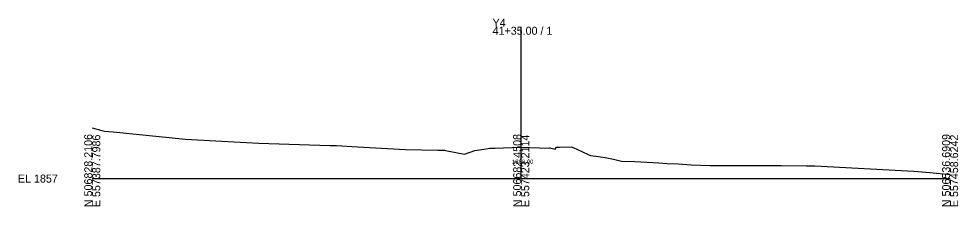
# Model space of a CAD drawing. Extents: x -26 to 1503, y -10 to 3040.
# Drawn here: x 1174.3 to 1502.8, y 490.3 to 556 of the extents above; entities that cross this region are included whole.
import ezdxf

# ---------------------------------------------------------------- set-up
doc = ezdxf.new("R2010")
doc.units = 0
for name, color, linetype in [('Exist Cross Section Cell', 7, 'Continuous'), ('Exist XS Ground Line', 7, 'Continuous'), ('Prop CMT Pvmt Course 1', 7, 'Continuous'), ('Prop CMT Shld Paved Course 1', 7, 'Continuous'), ('Prop XS Ditch Standard Text', 7, 'Continuous')]:
    doc.layers.add(name, color=color, linetype=linetype)

msp = doc.modelspace()

# ---------------------------------------------------------------- linework, layer by layer
at = {"layer": 'Exist Cross Section Cell'}
for p, q in [((1350, 500), (1350, 553.18)), ((1200, 500), (1350, 500)), ((1350, 500), (1500, 500))]:
    msp.add_line(p, q, dxfattribs=at)
at = {"layer": 'Exist XS Ground Line'}
msp.add_lwpolyline([(1200, 517.73), (1203.31, 516.86), (1204.3, 516.56), (1207.37, 516.33), (1232.64, 513.75), (1245.3, 513.12), (1258.23, 512.41), (1283.07, 511.61), (1285.43, 511.54), (1292.74, 511.12), (1309.49, 510.21), (1320.88, 509.96), (1322.85, 509.93), (1323.16, 509.92), (1323.51, 509.86), (1330.17, 508.53), (1333.84, 509.8), (1337.71, 510.46), (1339.04, 510.63), (1340.92, 510.7), (1349.8, 511.01), (1356.43, 510.8), (1359.87, 510.7), (1359.98, 510.71), (1361.86, 510.31), (1362.37, 510.97), (1363.38, 511.01), (1367.5, 511.15), (1368.43, 510.72), (1369.49, 510.29), (1373.45, 508.41), (1374.28, 508.12), (1377.1, 507.73), (1379.94, 507.29), (1382.28, 506.76), (1385.04, 506.07), (1389.78, 505.93), (1398.1, 505.55), (1401.08, 505.32), (1404.86, 505.2), (1409.44, 504.86), (1416.1, 504.6), (1435.15, 504.59), (1438.68, 504.56), (1440.95, 504.56), (1449.79, 504.46), (1451.75, 504.46), (1452.68, 504.46), (1487.35, 502.58), (1492.96, 502.14), (1500, 501.47)], dxfattribs=at)
at = {"layer": 'Prop CMT Pvmt Course 1'}
for points in [[(1350, 510.87), (1350, 511.12)], [(1350, 510.87), (1350, 511.12)], [(1360, 510.92), (1360, 510.67)]]:
    msp.add_lwpolyline(points, dxfattribs=at)
msp.add_lwpolyline([(1350, 510.87), (1350, 511), (1350, 511), (1350, 510.87)], close=True, dxfattribs=at)
msp.add_lwpolyline([(1350, 510.87), (1350, 511), (1350, 511), (1350, 510.87)], close=True, dxfattribs=at)
at = {"layer": 'Prop CMT Shld Paved Course 1'}
msp.add_lwpolyline([(1339.74, 510.66), (1340, 510.67)], dxfattribs=at)

# ---------------------------------------------------------------- texts
at = {"layer": 'Exist Cross Section Cell'}
for s, p in [('Y4', (1340, 553.18)), ('41+35.00 / 1', (1340, 550.38)), ('EL 1857', (1174, 498.6))]:
    msp.add_text(s, height=2.8, dxfattribs=at).set_placement(p)
for s, p in [('N 506828.2106', (1200, 490)), ('E 557387.7986', (1202.8, 490)), ('N 506682.4508', (1350, 490)), ('E 557423.2114', (1352.8, 490)), ('N 506536.6909', (1500, 490)), ('E 557458.6242', (1502.8, 490))]:
    msp.add_text(s, height=2.8, rotation=90, dxfattribs=at).set_placement(p)
at = {"layer": 'Prop XS Ditch Standard Text'}
msp.add_text('1868.00', height=1.5, dxfattribs=at).set_placement((1346.79, 505.15))

doc.saveas('drawing.dxf')
